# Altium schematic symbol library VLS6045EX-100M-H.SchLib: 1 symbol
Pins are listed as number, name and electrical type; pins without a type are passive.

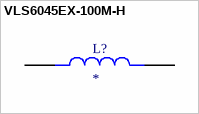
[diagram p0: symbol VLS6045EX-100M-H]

## VLS6045EX-100M-H
designator L?
Inductor Power Shielded Wirewound 10uH 20% 100KHz Ferrite 3.4A 0.0611Ohm DCR Automotive T/R; MF: TDK Corporation; MP: VLS6045EX-100M-H
footprint IND_VLS6045EX-100M-H
pins: 1, 2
